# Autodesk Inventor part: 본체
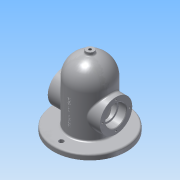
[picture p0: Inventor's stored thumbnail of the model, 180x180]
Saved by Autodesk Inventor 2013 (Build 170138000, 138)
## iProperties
Created: 2019-11
Part Number: 본체
Material: 알루미늄 6061
Document SubType Name: Modeling
Designer: Administrator
Density: 2.71 g/cm^3
Mass: 1110.22 g
Surface Area: 884.208 cm^2
Volume: 409.674 cm^3
Author: Administrator
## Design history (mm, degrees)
sketch "스케치1"
  geometry: C1 r 70 at (0, 0); 1 further point
  constraints: 1 centre point, 1 coincident
  dimensions: "d0" = 140 diameter of C1
extrude "돌출1" new body sketch "스케치1" distance "d2" = 10; taper "d3" = 0 deg
sketch "스케치2"
  geometry: L1 (0, 0)-(0, 55); L2 (0, 0)-(0, -55); C1 r 70 at (0, 0) reference; C2 r 4.5 at (0, 55); C3 r 4.5 at (0, -55); A1 r 55 centre (0, 0) between (0, 55) and (0, -55)
  constraints: 4 end point, 3 centre point, 3 coincident, 2 point on circle, 1 collinear, 1 vertical
  dimensions: "d4" = 110 diameter of A1; "d5" = 9 diameter of C2; "d6" = 9 diameter of C3
extrude "돌출2" cut sketch "스케치2" stored distance "d7" = 10; taper "d8" = 0 deg
sketch "스케치3"
  geometry: L1 (70, 10)-(-70, 10) reference; L2 (-70, 0)-(70, 0) reference; L3 (0, 10)-(0, 130); L4 (-40, 90)-(-40, 10); L5 (0, 10)-(-40, 10); A1 r 40 centre (0, 90) between (0, 130) and (-40, 90); 1 further point
  constraints: 6 end point, 3 perpendicular, 2 point on circle, 2 point on line, 1 centre point, 1 midpoint, 1 tangent
  dimensions: "d11" = 130 distance of L3.end point (0, 0); "d12" = 80 diameter of A1
revolve "회전1" sketch "스케치3" stored, may be unused: angle "d13" = 90 deg
node "작업 평면1"
sketch "스케치4"
  geometry: C1 r 40 at (0, 0) reference; C2 r 7.5 at (0, 0); 1 further point
  constraints: 1 centre point, 1 coincident
  dimensions: "d15" = 15 diameter of C2
extrude "돌출3" join sketch "스케치4" stored distance "d16" = 10; taper "d17" = 0 deg
sketch "스케치5"
  geometry: L1 (70, 10)-(-70, 10) reference; L2 (-70, 0)-(70, 0) reference; L3 (40, 90)-(-40, 90) reference; L4 (-40, 10)-(40, 10) reference; L5 (-7.5, 129.291)-(7.5, 129.291) reference; L6 (40, 90)-(-40, 90) reference; L7 (-7.5, 135)-(7.5, 135) reference; L8 (-7.5, 129.291)-(7.5, 129.291) reference; L9 (-40, 10)-(-40, 90) reference; L10 (40, 10)-(40, 90) reference; L11 (0, 0)-(0, 120); L12 (-30, 90)-(-30, 0); L13 (0, 0)-(-30, 0); A1 r 30 centre (0, 90) between (0, 120) and (-30, 90); 3 further points
  constraints: 6 end point, 2 parallel, 2 point on circle, 2 point on line, 1 centre point, 1 coincident, 1 perpendicular, 1 tangent, 1 other
  dimensions: "d18" = 60 diameter of A1
revolve "회전2" sketch "스케치5" stored, may be unused: angle "d19" = 90 deg
node "작업 평면2"
sketch "스케치6"
  geometry: L1 (40, 90)-(-40, 90) reference; L2 (-40, 10)-(40, 10) reference; L3 (-70, 0)-(70, 0) reference; C1 r 31 at (0, 50); 1 further point
  constraints: 1 centre point, 1 vertical alignment
  dimensions: "d21" = 62 diameter of C1; "d22" = 50 distance from line of C1.centre L3
extrude "돌출4" join sketch "스케치6" stored distance "d23" = 10; taper "d24" = 0 deg
sketch "스케치7"
  geometry: C1 r 31 at (0, 0) reference; C2 r 20 at (0, 0); 1 further point
  constraints: 1 centre point, 1 coincident
  dimensions: "d25" = 40 diameter of C2
extrude "돌출5" cut sketch "스케치7" distance "d26" = 15; taper "d27" = 0 deg
sketch "스케치8"
  geometry: C1 r 20 at (0, 0) reference; C2 r 16.5 at (0, 0); 1 further point
  constraints: 1 centre point, 1 coincident
  dimensions: "d28" = 33 diameter of C2
extrude "돌출6" cut sketch "스케치8" stored distance "d29" = 15; taper "d30" = 0 deg
sketch "스케치9" dims "d31" = 52
  geometry: L1 (0, 0)-(-26, 0); C1 r 31 at (0, 0) reference; 2 further points
  constraints: 2 coincident, 2 end point, 1 horizontal, 1 horizontal alignment, 2 other
hole "구멍1" sketch "스케치9" at (-26, 0) diameter "d33" = 3.242; stored, may be unused: countersink angle "d37" = 90 deg, drill point angle "d39" = 118 deg; dims "d34" = 8, "d35" = 4, "d36" = 2, "d38" = 10
sketch "스케치10"
  geometry: 1 further point
node "작업 평면3"
sketch "스케치11"
  geometry: C1 r 7.5 at (0, 0) reference; 1 further point
  constraints: 1 coincident
hole "구멍2" sketch "스케치11" at (0, 0) diameter "d44" = 5.188; stored, may be unused: countersink angle "d48" = 90 deg, drill point angle "d50" = 118 deg; dims "d45" = 8, "d46" = 4, "d47" = 2, "d49" = 10
node "작업 평면4"
sketch "스케치12"
  geometry: L1 (-70, 0)-(70, 0) reference; 2 further points
  constraints: 1 vertical alignment, 1 other
  dimensions: "d52" = 50 distance from line of point (0, 50) L1
extrude "돌출8" join sketch "스케치12" distance "d55" = 0.5; taper "d56" = 0 deg
fillet "모깎기1" dims "d57" = 3
fillet "모깎기2" dims "d58" = 3
fillet "모깎기3" dims "d59" = 3
chamfer "모따기1" distance "d60" = 1; stored, may be unused: second distance "d61" = 2, angle "d62" = 45 deg
fillet "모깎기4" dims "d63" = 0.3
node "솔리드1"
pattern_circular "원형 패턴1" dims angle "d41" = 360 deg
mirror "대칭1"
node "투영된 루프1"
node "투영된 루프2"
node "투영된 루프3"
node "투영된 루프4"
node "투영된 루프5"
node "투영된 루프6"
node "투영된 루프7"
other parameters: "d14" = 135
